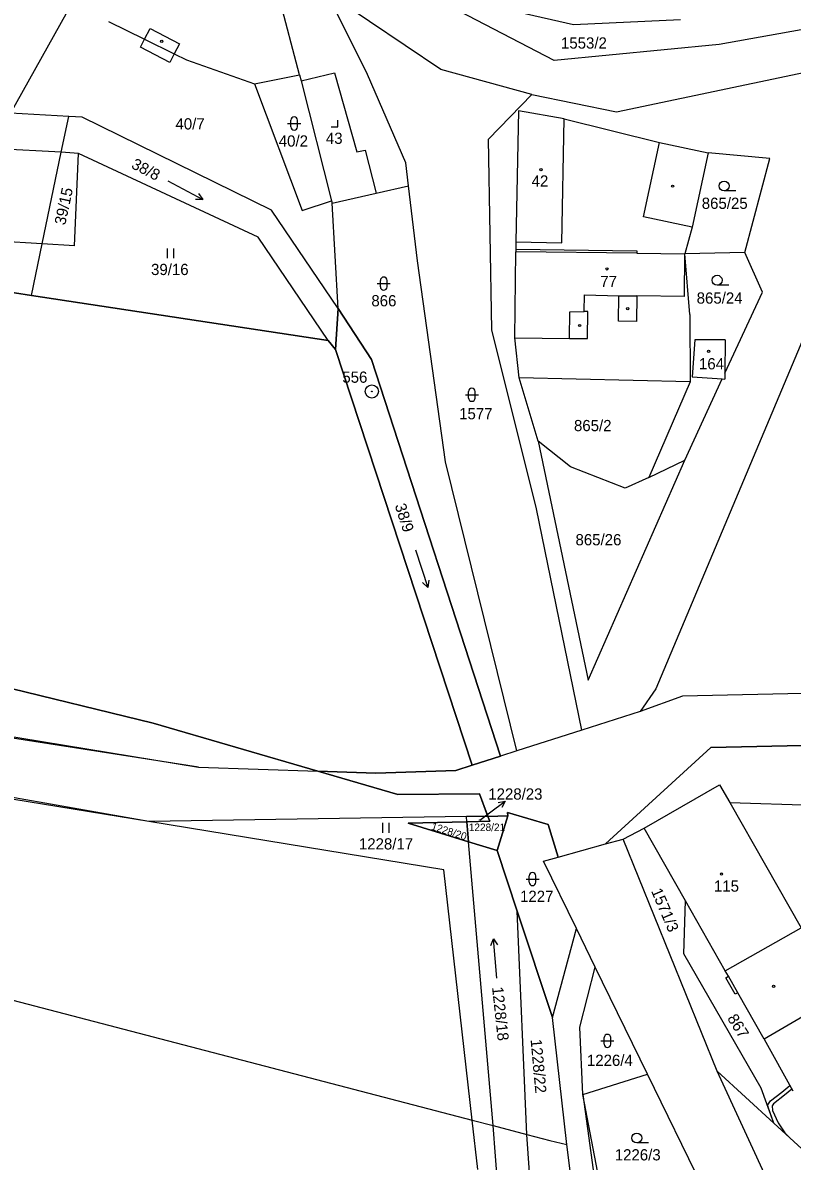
# Model space of a CAD drawing. Extents: x -801826 to -800592, y -1032871 to -1031813.
# Drawn here: x -801124.4 to -801007.9, y -1032553.2 to -1032380.8 of the extents above; entities that cross this region are included whole.
import ezdxf

# ---------------------------------------------------------------- set-up
doc = ezdxf.new("R2010")
doc.units = 0
for name, color, linetype in [('Vrstva 1', 7, 'Continuous'), ('Vrstva 16', 7, 'Continuous'), ('Vrstva 17', 7, 'Continuous'), ('Vrstva 18', 7, 'Continuous'), ('Vrstva 19', 7, 'Continuous'), ('Vrstva 24', 7, 'Continuous'), ('Vrstva 25', 7, 'Continuous'), ('Vrstva 27', 7, 'Continuous'), ('Vrstva 4', 7, 'Continuous')]:
    doc.layers.add(name, color=color, linetype=linetype)

msp = doc.modelspace()

# ---------------------------------------------------------------- linework, layer by layer
at = {"layer": 'Vrstva 1'}
for p, q in [((-801082.53, -1032388.65), (-801085.69, -1032376.62)), ((-801061.11, -1032387.87), (-801078.35, -1032376.25)), ((-801072.24, -1032388.64), (-801078.35, -1032376.25)), ((-801116.96, -1032377.78), (-801126.31, -1032394.49)), ((-801043.92, -1032386.49), (-801059.61, -1032378.37)), ((-801111.48, -1032380.61), (-801105.99, -1032383.29)), ((-801041, -1032381.1), (-801049.22, -1032379.24)), ((-801024.79, -1032380.35), (-801041, -1032381.1)), ((-801005.11, -1032381.61), (-801018.93, -1032384.07)), ((-801105.99, -1032383.29), (-801101.49, -1032385.48)), ((-801018.93, -1032384.07), (-801043.92, -1032386.49)), ((-801034.47, -1032394.27), (-800982.25, -1032383.32)), ((-801101.49, -1032385.48), (-801099.62, -1032386.39)), ((-801099.62, -1032386.39), (-801089.35, -1032390.06)), ((-801089.35, -1032390.06), (-801082.53, -1032388.65)), ((-801082.53, -1032388.65), (-801082.29, -1032389.57)), ((-801082.29, -1032389.57), (-801077.2, -1032388.36)), ((-801077.2, -1032388.36), (-801073.82, -1032400.35)), ((-801066.41, -1032401.98), (-801072.24, -1032388.64)), ((-801047.31, -1032391.63), (-801061.11, -1032387.87)), ((-801089.35, -1032390.06), (-801082.09, -1032409.24)), ((-801082.29, -1032389.57), (-801077.65, -1032407.75)), ((-801053.88, -1032398.41), (-801047.31, -1032391.63)), ((-801047.31, -1032391.63), (-801034.47, -1032394.27)), ((-801049.33, -1032394.14), (-801049.72, -1032413.96)), ((-801042.41, -1032395.32), (-801049.33, -1032394.14)), ((-801117.46, -1032394.97), (-801126.31, -1032394.49)), ((-801118.61, -1032400.4), (-801117.46, -1032394.97)), ((-801115.44, -1032395.09), (-801117.46, -1032394.97)), ((-801086.78, -1032409.17), (-801115.44, -1032395.09)), ((-801042.41, -1032395.32), (-801027.98, -1032398.9)), ((-801118.61, -1032400.4), (-801160.03, -1032398.16)), ((-801053.37, -1032427.27), (-801053.88, -1032398.41)), ((-801027.98, -1032398.9), (-801020.61, -1032400.48)), ((-801121.52, -1032414.28), (-801118.61, -1032400.4)), ((-801116, -1032400.57), (-801118.61, -1032400.4)), ((-801116.6, -1032414.57), (-801116, -1032400.57)), ((-801088.76, -1032413.24), (-801116, -1032400.57)), ((-801073.82, -1032400.35), (-801072.56, -1032400.07)), ((-801072.56, -1032400.07), (-801070.89, -1032406.6)), ((-801020.61, -1032400.48), (-801023.03, -1032411.73)), ((-801011.28, -1032401.35), (-801020.61, -1032400.48)), ((-801015.03, -1032415.56), (-801011.28, -1032401.35)), ((-801065.99, -1032405.49), (-801066.41, -1032401.98)), ((-801070.89, -1032406.6), (-801065.99, -1032405.49)), ((-801064.63, -1032416.83), (-801065.99, -1032405.49)), ((-801082.09, -1032409.24), (-801077.65, -1032407.75)), ((-801077.65, -1032407.75), (-801077.56, -1032408.11)), ((-801077.56, -1032408.11), (-801070.89, -1032406.6)), ((-801076.67, -1032424.04), (-801077.56, -1032408.11)), ((-801076.67, -1032424.04), (-801086.78, -1032409.17)), ((-801121.52, -1032414.28), (-801163.36, -1032411.83)), ((-801078.19, -1032428.92), (-801088.76, -1032413.24)), ((-801023.03, -1032411.73), (-801024.14, -1032415.78)), ((-801123.15, -1032422.09), (-801121.52, -1032414.28)), ((-801116.6, -1032414.57), (-801121.52, -1032414.28)), ((-801049.72, -1032413.96), (-801049.72, -1032415.09)), ((-801049.72, -1032415.09), (-801049.72, -1032415.49)), ((-801049.72, -1032415.09), (-801031.39, -1032415.3)), ((-801164.43, -1032415.66), (-801123.15, -1032422.09)), ((-801123.15, -1032422.09), (-801164.43, -1032415.66)), ((-801060.38, -1032447.29), (-801064.63, -1032416.83)), ((-801049.89, -1032428.48), (-801049.72, -1032415.49)), ((-801031.39, -1032415.3), (-801031.4, -1032415.7)), ((-801031.4, -1032415.7), (-801024.14, -1032415.78)), ((-801015.03, -1032415.56), (-801024.14, -1032415.78)), ((-801023.39, -1032424.94), (-801024.14, -1032415.78)), ((-801012.39, -1032421.59), (-801015.03, -1032415.56)), ((-801018.06, -1032433.84), (-801012.39, -1032421.59)), ((-801123.15, -1032422.09), (-801078.19, -1032428.92)), ((-801078.19, -1032428.92), (-801123.15, -1032422.09)), ((-801077.08, -1032430.26), (-801076.67, -1032424.04)), ((-801076.67, -1032424.04), (-801077.08, -1032430.26)), ((-801076.67, -1032424.04), (-801071.61, -1032431.8)), ((-801071.61, -1032431.8), (-801076.67, -1032424.04)), ((-801004.8, -1032425.27), (-801028.52, -1032481.63)), ((-801023.39, -1032424.94), (-801023.32, -1032435.14)), ((-801078.19, -1032428.92), (-801077.08, -1032430.26)), ((-801077.08, -1032430.26), (-801078.19, -1032428.92)), ((-801046.62, -1032454.41), (-801053.37, -1032427.27)), ((-801049.25, -1032434.54), (-801049.89, -1032428.48)), ((-801022.64, -1032428.78), (-801023.03, -1032434.39)), ((-801018.02, -1032428.82), (-801022.64, -1032428.78)), ((-801018.02, -1032428.82), (-801018.06, -1032433.84)), ((-801077.08, -1032430.26), (-801056.36, -1032493.2)), ((-801077.08, -1032430.26), (-801056.36, -1032493.2)), ((-801056.36, -1032493.2), (-801077.08, -1032430.26)), ((-801071.61, -1032431.8), (-801052.07, -1032491.83)), ((-801052.07, -1032491.83), (-801071.61, -1032431.8)), ((-801018.06, -1032433.84), (-801018.07, -1032434.73)), ((-801046.36, -1032444.13), (-801049.25, -1032434.54)), ((-801023.32, -1032435.14), (-801049.25, -1032434.54)), ((-801023.32, -1032435.14), (-801029.59, -1032449.62)), ((-801024.15, -1032447.01), (-801018.46, -1032434.7)), ((-801023.03, -1032434.39), (-801018.46, -1032434.7)), ((-801018.46, -1032434.7), (-801018.07, -1032434.73)), ((-801046.36, -1032444.13), (-801038.79, -1032480.32)), ((-801041.47, -1032448.01), (-801046.36, -1032444.13)), ((-801049.57, -1032491.03), (-801060.38, -1032447.29)), ((-801038.79, -1032480.32), (-801024.15, -1032447.01)), ((-801029.59, -1032449.62), (-801024.15, -1032447.01)), ((-801033.18, -1032451.26), (-801041.47, -1032448.01)), ((-801029.59, -1032449.62), (-801033.18, -1032451.26)), ((-801342.15, -1032453.77), (-801097.8, -1032493.48)), ((-801039.76, -1032487.9), (-801046.62, -1032454.41)), ((-801104.67, -1032486.84), (-801217.1, -1032459.5)), ((-801217.1, -1032459.5), (-801104.67, -1032486.84)), ((-801097.8, -1032493.48), (-801268.54, -1032467.11)), ((-801105.37, -1032501.75), (-801290.52, -1032469)), ((-801028.52, -1032481.63), (-801030.9, -1032485.06)), ((-800994.76, -1032482.06), (-801024.5, -1032482.76)), ((-800994.76, -1032482.06), (-801024.5, -1032482.76)), ((-801024.5, -1032482.76), (-801030.9, -1032485.06)), ((-801024.5, -1032482.76), (-801030.9, -1032485.06)), ((-801030.9, -1032485.06), (-801039.76, -1032487.9)), ((-801030.9, -1032485.06), (-801039.76, -1032487.9)), ((-801287.22, -1032486.69), (-801056.37, -1032546.95)), ((-801079.73, -1032494.11), (-801104.67, -1032486.84)), ((-801104.67, -1032486.84), (-801079.73, -1032494.11)), ((-801039.76, -1032487.9), (-801049.57, -1032491.03)), ((-801039.76, -1032487.9), (-801049.57, -1032491.03)), ((-801020.2, -1032490.51), (-801036.17, -1032505.13)), ((-801036.17, -1032505.13), (-801020.2, -1032490.51)), ((-800997.78, -1032490.01), (-801020.2, -1032490.51)), ((-801020.2, -1032490.51), (-800997.78, -1032490.01)), ((-801052.07, -1032491.83), (-801056.36, -1032493.2)), ((-801056.36, -1032493.2), (-801052.07, -1032491.83)), ((-801052.07, -1032491.83), (-801056.36, -1032493.2)), ((-801049.57, -1032491.03), (-801052.07, -1032491.83)), ((-801049.57, -1032491.03), (-801052.07, -1032491.83)), ((-801097.8, -1032493.48), (-801079.73, -1032494.11)), ((-801067.6, -1032497.64), (-801079.73, -1032494.11)), ((-801079.73, -1032494.11), (-801070.96, -1032494.41)), ((-801079.73, -1032494.11), (-801070.96, -1032494.41)), ((-801070.96, -1032494.41), (-801079.73, -1032494.11)), ((-801079.73, -1032494.11), (-801067.6, -1032497.64)), ((-801058.83, -1032493.99), (-801070.96, -1032494.41)), ((-801070.96, -1032494.41), (-801058.83, -1032493.99)), ((-801058.83, -1032493.99), (-801070.96, -1032494.41)), ((-801056.36, -1032493.2), (-801058.83, -1032493.99)), ((-801058.83, -1032493.99), (-801056.36, -1032493.2)), ((-801056.36, -1032493.2), (-801058.83, -1032493.99)), ((-801105.37, -1032501.75), (-801144.19, -1032495.42)), ((-801055.25, -1032497.52), (-801067.6, -1032497.64)), ((-801067.6, -1032497.64), (-801055.25, -1032497.52)), ((-801053.97, -1032500.96), (-801055.25, -1032497.52)), ((-801030.32, -1032502.75), (-801018.86, -1032496.19)), ((-801018.86, -1032496.19), (-801017.33, -1032498.87)), ((-801017.33, -1032498.87), (-801006.53, -1032517.81)), ((-801017.33, -1032498.87), (-801004.72, -1032499.25)), ((-801057.24, -1032500.98), (-801105.37, -1032501.75)), ((-801053.97, -1032500.96), (-801057.24, -1032500.98)), ((-801057.17, -1032501.78), (-801057.24, -1032500.98)), ((-801050.95, -1032500.86), (-801053.97, -1032500.96)), ((-801050.95, -1032500.86), (-801053.97, -1032500.96)), ((-801053.97, -1032500.96), (-801050.95, -1032500.86)), ((-801053.69, -1032501.7), (-801053.97, -1032500.96)), ((-801053.97, -1032500.96), (-801053.69, -1032501.7)), ((-801052.59, -1032506.13), (-801050.95, -1032500.86)), ((-801050.95, -1032500.86), (-801052.59, -1032506.13)), ((-801052.59, -1032506.13), (-801050.95, -1032500.86)), ((-801050.95, -1032500.86), (-801051, -1032500.39)), ((-801051, -1032500.39), (-801044.84, -1032502.18)), ((-801044.84, -1032502.18), (-801051, -1032500.39)), ((-801051, -1032500.39), (-801050.95, -1032500.86)), ((-801050.95, -1032500.86), (-801051, -1032500.39)), ((-801051, -1032500.39), (-801044.84, -1032502.18)), ((-801060.65, -1032509.04), (-801105.37, -1032501.75)), ((-801066.04, -1032501.97), (-801057.17, -1032501.78)), ((-801057.17, -1032501.78), (-801066.04, -1032501.97)), ((-801056.89, -1032504.8), (-801066.04, -1032501.97)), ((-801066.04, -1032501.97), (-801056.89, -1032504.8)), ((-801057.17, -1032501.78), (-801053.69, -1032501.7)), ((-801053.69, -1032501.7), (-801057.17, -1032501.78)), ((-801056.89, -1032504.8), (-801057.17, -1032501.78)), ((-801056.89, -1032504.8), (-801057.17, -1032501.78)), ((-801057.17, -1032501.78), (-801056.89, -1032504.8)), ((-801044.84, -1032502.18), (-801043.31, -1032507.13)), ((-801043.31, -1032507.13), (-801044.84, -1032502.18)), ((-801044.84, -1032502.18), (-801043.31, -1032507.13)), ((-801033.49, -1032504.39), (-801030.32, -1032502.75)), ((-801024.05, -1032513.75), (-801030.32, -1032502.75)), ((-801036.17, -1032505.13), (-801033.49, -1032504.39)), ((-801019.25, -1032539.53), (-801033.49, -1032504.39)), ((-801052.59, -1032506.13), (-801056.89, -1032504.8)), ((-801053.17, -1032547.78), (-801056.89, -1032504.8)), ((-801056.89, -1032504.8), (-801052.59, -1032506.13)), ((-801049.56, -1032515.32), (-801052.59, -1032506.13)), ((-801052.59, -1032506.13), (-801049.56, -1032515.32)), ((-801043.31, -1032507.13), (-801036.17, -1032505.13)), ((-801043.31, -1032507.13), (-801036.17, -1032505.13)), ((-801045.57, -1032507.76), (-801043.31, -1032507.13)), ((-801045.57, -1032507.76), (-801043.31, -1032507.13)), ((-801040.57, -1032517.94), (-801045.57, -1032507.76)), ((-801040.57, -1032517.94), (-801045.57, -1032507.76)), ((-801056.37, -1032546.95), (-801060.65, -1032509.04)), ((-801024.27, -1032521.76), (-801024.05, -1032513.75)), ((-801018.01, -1032524.35), (-801024.05, -1032513.75)), ((-801048.06, -1032549.12), (-801049.56, -1032515.32)), ((-801044.21, -1032531.41), (-801049.56, -1032515.32)), ((-801049.56, -1032515.32), (-801044.21, -1032531.41)), ((-801044.21, -1032531.41), (-801040.57, -1032517.94)), ((-801044.21, -1032531.41), (-801040.57, -1032517.94)), ((-801037.7, -1032523.81), (-801040.57, -1032517.94)), ((-801012.55, -1032542.12), (-801024.27, -1032521.76)), ((-801040.05, -1032532.85), (-801037.7, -1032523.81)), ((-801029.77, -1032540.01), (-801037.7, -1032523.81)), ((-801017.54, -1032525.17), (-801018.01, -1032524.35)), ((-801017.93, -1032525.4), (-801017.54, -1032525.17)), ((-801016.51, -1032527.87), (-801017.93, -1032525.4)), ((-801016.12, -1032527.65), (-801016.51, -1032527.87)), ((-801012.11, -1032534.69), (-801016.12, -1032527.65)), ((-801042.02, -1032550.66), (-801044.21, -1032531.41)), ((-801039.61, -1032543.05), (-801040.05, -1032532.85)), ((-801012.11, -1032534.69), (-801007.79, -1032542.51)), ((-801039.61, -1032543.05), (-801029.77, -1032540.01)), ((-801020.95, -1032558.06), (-801029.77, -1032540.01)), ((-801010.64, -1032547.43), (-801019.25, -1032539.53)), ((-801009.42, -1032560.77), (-801019.25, -1032539.53)), ((-801010.64, -1032547.43), (-801012.55, -1032542.12)), ((-801035.88, -1032562.46), (-801039.61, -1032543.05)), ((-801039.61, -1032543.05), (-801032.64, -1032593.34)), ((-801055.52, -1032554.44), (-801056.37, -1032546.95)), ((-801056.37, -1032546.95), (-801053.17, -1032547.78)), ((-801048.16, -1032614.25), (-801053.17, -1032547.78)), ((-801053.17, -1032547.78), (-801048.06, -1032549.12)), ((-800998.43, -1032558.61), (-801010.64, -1032547.43)), ((-801048.06, -1032549.12), (-801044.58, -1032550.03)), ((-801043.7, -1032614.64), (-801048.06, -1032549.12)), ((-801044.58, -1032550.03), (-801042.02, -1032550.66)), ((-801036.42, -1032593.26), (-801042.02, -1032550.66))]:
    msp.add_line(p, q, dxfattribs=at)
msp.add_lwpolyline([(-801055.25, -1032497.52), (-801054.07, -1032500.68), (-801053.97, -1032500.96)], dxfattribs=at)
at = {"layer": 'Vrstva 16'}
for p, q in [((-801053.74, -1032500.43), (-801051.34, -1032498.63)), ((-801055.18, -1032501.52), (-801053.74, -1032500.43))]:
    msp.add_line(p, q, dxfattribs=at)
msp.add_lwpolyline([(-801052.44, -1032498.83), (-801051.34, -1032498.63), (-801051.84, -1032499.63)], dxfattribs=at)
at = {"layer": 'Vrstva 24'}
for radius in [1, 0.0439]:
    msp.add_circle((-801071.56, -1032436.61), radius, dxfattribs=at)
at = {"layer": 'Vrstva 25'}
for p, q in [((-801084.32, -1032396.03), (-801082.32, -1032396.03)), ((-801083.82, -1032396.53), (-801083.82, -1032395.53)), ((-801082.82, -1032396.53), (-801082.82, -1032395.53)), ((-801076.73, -1032396.54), (-801076.73, -1032395.54)), ((-801077.73, -1032396.54), (-801076.73, -1032396.54)), ((-801102.48, -1032404.74), (-801097.18, -1032407.56)), ((-801016.43, -1032406.25), (-801018.18, -1032406.25)), ((-801102.58, -1032414.95), (-801102.58, -1032416.45)), ((-801101.56, -1032416.45), (-801101.56, -1032414.95)), ((-801070.76, -1032420.29), (-801068.76, -1032420.29)), ((-801070.26, -1032420.79), (-801070.26, -1032419.79)), ((-801069.26, -1032420.79), (-801069.26, -1032419.79)), ((-801017.49, -1032420.52), (-801019.24, -1032420.52)), ((-801057.39, -1032437.11), (-801055.39, -1032437.11)), ((-801056.89, -1032437.61), (-801056.89, -1032436.61)), ((-801055.89, -1032437.61), (-801055.89, -1032436.61)), ((-801064.96, -1032460.61), (-801063.08, -1032466.31)), ((-801069.94, -1032501.95), (-801069.94, -1032503.45)), ((-801068.92, -1032503.45), (-801068.92, -1032501.95)), ((-801047.7, -1032510.94), (-801047.7, -1032509.94)), ((-801046.7, -1032510.94), (-801046.7, -1032509.94)), ((-801048.2, -1032510.44), (-801046.2, -1032510.44)), ((-801052.62, -1032525.46), (-801053.12, -1032519.48)), ((-801036.87, -1032534.96), (-801034.87, -1032534.96)), ((-801036.37, -1032535.46), (-801036.37, -1032534.46)), ((-801035.37, -1032535.46), (-801035.37, -1032534.46)), ((-801029.66, -1032550.41), (-801031.41, -1032550.41))]:
    msp.add_line(p, q, dxfattribs=at)
for points in [[(-801097.83, -1032406.65), (-801097.18, -1032407.56), (-801098.3, -1032407.53)], [(-801062.92, -1032465.2), (-801063.08, -1032466.31), (-801063.87, -1032465.52)], [(-801053.54, -1032520.52), (-801053.12, -1032519.48), (-801052.54, -1032520.43)]]:
    msp.add_lwpolyline(points, dxfattribs=at)
for centre, radius in [((-801103.4, -1032383.62), 0.175), ((-801045.93, -1032403.05), 0.175), ((-801018.18, -1032405.5), 0.75), ((-801025.99, -1032405.53), 0.175), ((-801035.93, -1032418.05), 0.175), ((-801019.24, -1032419.77), 0.75), ((-801032.78, -1032424.1), 0.175), ((-801040.09, -1032426.63), 0.175), ((-801020.53, -1032430.52), 0.175), ((-801018.58, -1032509.7), 0.175), ((-801010.69, -1032526.71), 0.175), ((-801031.41, -1032549.66), 0.75)]:
    msp.add_circle(centre, radius, dxfattribs=at)
for centre, start, end in [((-801083.32, -1032395.53), 0, 180), ((-801083.32, -1032396.53), 180, 0), ((-801069.76, -1032419.79), 0, 180), ((-801069.76, -1032420.79), 180, 0), ((-801056.39, -1032436.61), 0, 180), ((-801056.39, -1032437.61), 180, 0), ((-801047.2, -1032509.94), 0, 180), ((-801047.2, -1032510.94), 180, 0), ((-801035.87, -1032534.46), 0, 180), ((-801035.87, -1032535.46), 180, 0)]:
    msp.add_arc(centre, 0.5, start, end, dxfattribs=at)
at = {"layer": 'Vrstva 27'}
msp.add_lwpolyline([(-801009.43, -1032542.72), (-801008.24, -1032541.7), (-801007.93, -1032542.25), (-801009.02, -1032543.18), (-801010.69, -1032544.46), (-801010.91, -1032544.79), (-801010.85, -1032545.51), (-801010.01, -1032547.34), (-801008.99, -1032548.85), (-801008.44, -1032549.44), (-801010.64, -1032547.43), (-801011.52, -1032544.98), (-801011.55, -1032544.62), (-801011.17, -1032544.05), (-801009.43, -1032542.72)], dxfattribs=at)
at = {"layer": 'Vrstva 4'}
for p, q in [((-801105.99, -1032383.29), (-801105.14, -1032381.67)), ((-801105.14, -1032381.67), (-801100.71, -1032383.98)), ((-801106.62, -1032384.5), (-801105.99, -1032383.29)), ((-801100.71, -1032383.98), (-801101.49, -1032385.48)), ((-801102.19, -1032386.82), (-801106.62, -1032384.5)), ((-801101.49, -1032385.48), (-801102.19, -1032386.82)), ((-801042.77, -1032414.09), (-801042.41, -1032395.32)), ((-801030.4, -1032410.15), (-801027.98, -1032398.9)), ((-801023.03, -1032411.73), (-801030.4, -1032410.15)), ((-801049.72, -1032413.96), (-801042.77, -1032414.09)), ((-801031.4, -1032415.7), (-801049.72, -1032415.49)), ((-801024.21, -1032422.24), (-801024.14, -1032415.78)), ((-801039.39, -1032424.52), (-801039.36, -1032421.97)), ((-801039.36, -1032421.97), (-801034.12, -1032422.13)), ((-801034.17, -1032425.98), (-801034.12, -1032422.13)), ((-801034.12, -1032422.13), (-801031.42, -1032422.16)), ((-801031.42, -1032422.16), (-801031.46, -1032426.01)), ((-801024.21, -1032422.24), (-801031.42, -1032422.16)), ((-801041.6, -1032428.59), (-801041.55, -1032424.54)), ((-801041.55, -1032424.54), (-801039.39, -1032424.52)), ((-801038.84, -1032424.53), (-801039.39, -1032424.52)), ((-801038.9, -1032428.62), (-801038.84, -1032424.53)), ((-801031.46, -1032426.01), (-801034.17, -1032425.98)), ((-801049.89, -1032428.48), (-801041.6, -1032428.59)), ((-801041.6, -1032428.59), (-801038.9, -1032428.62)), ((-801018.01, -1032524.35), (-801006.53, -1032517.81)), ((-801016.12, -1032527.65), (-801017.54, -1032525.17)), ((-801004.24, -1032530.12), (-801012.11, -1032534.69))]:
    msp.add_line(p, q, dxfattribs=at)

# ---------------------------------------------------------------- texts
at = {"layer": 'Vrstva 16'}
msp.add_text('1228/23', height=1.7, dxfattribs=at).set_placement((-801053.92, -1032498.42))
at = {"layer": 'Vrstva 17'}
msp.add_text('556', height=1.7, dxfattribs=at).set_placement((-801076.03, -1032435.3))
at = {"layer": 'Vrstva 18'}
for s, height, p in [('1553/2', 1.7, (-801042.9, -1032384.7)), ('40/7', 1.7, (-801101.31, -1032396.95)), ('40/2', 1.7, (-801085.66, -1032399.54)), ('865/25', 1.7, (-801021.57, -1032408.97)), ('39/16', 1.7, (-801105.01, -1032418.99)), ('866', 1.7, (-801071.63, -1032423.73)), ('865/24', 1.7, (-801022.34, -1032423.32)), ('1577', 1.7, (-801058.33, -1032440.83)), ('865/2', 1.7, (-801040.93, -1032442.63)), ('865/26', 1.7, (-801040.7, -1032459.91)), ('1228/21', 1.14, (-801056.87, -1032503.18)), ('1228/23', 0.1, (-801055.43, -1032501.52)), ('1228/17', 1.7, (-801073.52, -1032505.97)), ('1227', 1.7, (-801049.1, -1032513.91)), ('1226/4', 1.7, (-801038.97, -1032538.74)), ('1226/3', 1.7, (-801034.75, -1032553.05))]:
    msp.add_text(s, height=height, dxfattribs=at).set_placement(p)
for s, height, rotation, p in [('38/8', 1.7, 332.5774, (-801108.13, -1032402.72)), ('39/15', 1.7, 77.8807, (-801118.02, -1032411.52)), ('38/9', 1.7, 287.7264, (-801068.1, -1032453.87)), ('1228/20', 1.14, 342.512, (-801062.65, -1032502.94)), ('1571/3', 1.7, 293.0596, (-801029.27, -1032512.25)), ('1228/18', 1.7, 276.159, (-801053.35, -1032526.84)), ('867', 1.7, 302.0486, (-801017.77, -1032531.54)), ('1228/22', 1.7, 275.1661, (-801047.51, -1032534.76))]:
    msp.add_text(s, height=height, rotation=rotation, dxfattribs=at).set_placement(p)
at = {"layer": 'Vrstva 19'}
for s, p in [('43', (-801078.52, -1032399.13)), ('42', (-801047.35, -1032405.6)), ('77', (-801036.94, -1032420.81)), ('164', (-801021.99, -1032433.27)), ('115', (-801019.72, -1032512.36))]:
    msp.add_text(s, height=1.7, dxfattribs=at).set_placement(p)

doc.saveas('drawing.dxf')
